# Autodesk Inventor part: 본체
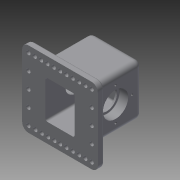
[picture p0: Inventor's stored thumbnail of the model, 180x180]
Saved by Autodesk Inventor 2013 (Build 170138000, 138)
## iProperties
Created: 2018-11
Part Number: 본체
Material: 일반
Document SubType Name: Modeling
Designer: Administrator
Density: 1 g/cm^3
Author: Administrator
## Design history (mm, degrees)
sketch "스케치1"
  geometry: L1 (60, -60)-(-60, -60); L2 (-60, -60)-(-60, 60); L3 (-60, 60)-(60, 60); L4 (60, 60)-(60, -60); 2 further points
  constraints: 8 end point, 2 parallel, 1 coincident, 1 horizontal, 1 perpendicular
  dimensions: "d0" = 120 distance of L3.end L1.start; "d2" = 120 distance between parallel lines of L2 L4; "d3" = 60 distance from line of point (0, 0) L4; "d4" = 60 distance from line of point (0, 0) L1
extrude "돌출1" new body sketch "스케치1" distance "d5" = 10; taper "d6" = 0 deg
sketch "스케치2"
  geometry: L1 (60, 60)-(-60, 60) reference; L2 (60, -60)-(60, 60) reference; L3 (-40, 40)-(40, 40); L4 (40, 40)-(40, -40); L5 (40, -40)-(-40, -40); L6 (-40, -40)-(-40, 40); 2 further points
  constraints: 8 end point, 2 parallel, 1 coincident, 1 horizontal, 1 perpendicular
  dimensions: "d7" = 80 distance between parallel lines of L4 L6; "d9" = 80 distance between parallel lines of L5 L3; "d10" = 20 distance between parallel lines of L1 L3; "d11" = 20 distance between parallel lines of L2 L4
extrude "돌출2" join sketch "스케치2" distance "d12" = 80; taper "d13" = 0 deg
sketch "스케치3"
  geometry: L1 (60, -60)-(60, 60) reference; L2 (60, 60)-(-60, 60) reference; L3 (-23, 30)-(23, 30); L4 (23, 30)-(23, -30); L5 (23, -30)-(-23, -30); L6 (-23, -30)-(-23, 30); 2 further points
  constraints: 8 end point, 2 parallel, 1 coincident, 1 horizontal, 1 perpendicular
  dimensions: "d14" = 46 distance between parallel lines of L4 L6; "d16" = 60 distance between parallel lines of L5 L3; "d17" = 30 distance between parallel lines of L2 L3; "d18" = 37 distance between parallel lines of L1 L4
extrude "돌출3" cut sketch "스케치3" distance "d19" = 80; taper "d20" = 0 deg
sketch "스케치4"
  geometry: C1 r 7.5 at (0, 0); 1 further point
  constraints: 1 centre point, 1 coincident
  dimensions: "d21" = 15 diameter of C1
extrude "돌출4" join sketch "스케치4" distance "d22" = 5; taper "d23" = 0 deg
sketch "스케치5"
  geometry: C1 r 7.5 at (0, 0) reference; C2 r 3 at (0, 0)
  constraints: 1 centre point, 1 coincident
  dimensions: "d24" = 6 diameter of C2
extrude "돌출5" cut sketch "스케치5" distance "d25" = 50; taper "d26" = 0 deg
sketch "스케치6"
  geometry: L1 (80, 0)-(0, 0) reference; L2 (80, 0)-(80, 80) reference; L3 (0, 80)-(80, 80) reference; L4 (0, 0)-(0, 80) reference; L5 (40, -10)-(40, 38); C1 r 20 at (40, 38)
  constraints: 2 end point, 1 centre point, 1 coincident, 1 parallel
  dimensions: "d27" = 48 distance of L5.start L5.end; "d28" = 40 diameter of C1
extrude "돌출6" cut sketch "스케치6" distance "d29" = 14; taper "d30" = 0 deg
sketch "스케치7"
  geometry: C1 r 20 at (0, 0) reference; C2 r 16.5 at (0, 0); 1 further point
  constraints: 1 centre point, 1 coincident
  dimensions: "d31" = 33 diameter of C2
extrude "돌출7" cut sketch "스케치7" distance "d32" = 3; taper "d33" = 0 deg
sketch "스케치9"
  geometry: L1 (40, 64)-(40, 12); C1 r 20 at (40, 38) reference; A1 r 26 centre (40, 38) between (40, 64) and (40, 12); 2 further points
  constraints: 2 coincident, 2 end point, 2 point on circle, 1 centre point
  dimensions: "d34" = 52 diameter of A1
hole "구멍1" sketch "스케치9" at (40, 64) diameter "d35" = 3.242; stored, may be unused: countersink angle "d39" = 82 deg, drill point angle "d41" = 118 deg; dims "d36" = 8, "d37" = 3.023, "d38" = 2, "d40" = 10
feature "스레드1" dims "d45" = 10, "d46" = 0
sketch "스케치10"
  geometry: L1 (-40, -40)-(-40, 40) reference; L2 (60, 60)-(-60, 60) reference; L3 (-60, 60)-(-60, -60) reference; L4 (60, -60)-(60, 60) reference; L5 (-60, 25)-(-40, 25); C1 r 3.3 at (-50, 50); C2 r 3.3 at (-39.046, 50); C3 r 3.3 at (-29.046, 50); C4 r 3.3 at (-19.046, 50); C5 r 3.3 at (-9.046, 50); C6 r 3.3 at (0, 50); C7 r 3.3 at (-50, 25); C8 r 3.3 at (-50, 0); C9 r 3.3 at (-50, -50); C10 r 3.3 at (-40, -50); C11 r 3.3 at (-30, -50); C12 r 3.3 at (-20, -50); C13 r 3.3 at (-10, -50); C14 r 3.3 at (0, -50); C15 r 3.3 at (-50, -25); C16 r 3.3 at (50, 50); C17 r 3.3 at (40, 50); C18 r 3.3 at (30, 50); C19 r 3.3 at (20, 50); C20 r 3.3 at (10, 50); C21 r 3.3 at (10, -50); C22 r 3.3 at (20, -50); C23 r 3.3 at (30, -50); C24 r 3.3 at (40, -50); C25 r 3.3 at (50, -50); C26 r 3.3 at (50, -25); C27 r 3.3 at (50, 25); C28 r 3.3 at (50, 0); 1 further point
  constraints: 28 centre point, 20 equal radius, 2 end point, 2 point on line, 1 midpoint, 1 perpendicular
  dimensions: "d54" = 6.6 diameter of C1; "d56" = 6.6 diameter of C3; "d57" = 6.6 diameter of C4; "d58" = 6.6 diameter of C5; "d59" = 6.6 diameter of C6; "d60" = 6.6 diameter of C7; "d61" = 6.6 diameter of C8; "d64" = 6.6 diameter of C15; "d67" = 35 distance between parallel lines of L2 L5; "d68" = 10 distance from line of C16.centre L2; "d69" = 10 distance from line of C16.centre L4; "d70" = 35 distance from line of C27.centre L2; "d71" = 10 distance from line of C27.centre L4; "d72" = 60 distance from line of C28.centre L2; "d73" = 10 distance from line of C28.centre L4; "d74" = 85 distance from line of C26.centre L2; "d75" = 10 distance from line of C26.centre L4; "d76" = 110 distance from line of C25.centre L2; "d77" = 10 distance from line of C25.centre L4; "d78" = 10 distance from line of C17.centre L2; "d79" = 20 distance from line of C17.centre L4; "d80" = 110 distance from line of C24.centre L2; "d81" = 20 distance from line of C24.centre L4; "d82" = 10 distance from line of C18.centre L2; "d83" = 30 distance from line of C18.centre L4; "d84" = 110 distance from line of C23.centre L2; "d85" = 30 distance from line of C23.centre L4; "d86" = 10 distance from line of C19.centre L2; "d87" = 40 distance from line of C19.centre L4; "d88" = 110 distance from line of C22.centre L2; "d89" = 40 distance from line of C22.centre L4; "d90" = 10 distance from line of C20.centre L2; "d91" = 50 distance from line of C20.centre L4; "d92" = 110 distance from line of C21.centre L2; "d93" = 50 distance from line of C21.centre L4; "d94" = 10 distance from line of C6.centre L2; "d95" = 60 distance from line of C6.centre L4; "d96" = 110 distance from line of C14.centre L2; "d97" = 60 distance from line of C14.centre L4; "d98" = 10 distance from line of C5.centre L2; "d99" = 69.04638 distance from line of C5.centre L4; "d100" = 110 distance from line of C13.centre L2; "d101" = 70 distance from line of C13.centre L4; "d102" = 10 distance from line of C4.centre L2; "d103" = 79.04638 distance from line of C4.centre L4; "d104" = 110 distance from line of C12.centre L2; "d105" = 80 distance from line of C12.centre L4; "d106" = 10 distance from line of C3.centre L2; "d107" = 89.04638 distance from line of C3.centre L4; "d108" = 110 distance from line of C11.centre L2; "d109" = 90 distance from line of C11.centre L4; "d110" = 10 distance from line of C2.centre L2; "d111" = 99.04638 distance from line of C2.centre L4; "d112" = 110 distance from line of C10.centre L2; "d113" = 100 distance from line of C10.centre L4; "d114" = 10 distance from line of C1.centre L2; "d115" = 110 distance from line of C1.centre L4; "d116" = 60 distance from line of C8.centre L2; "d117" = 110 distance from line of C8.centre L4; "d118" = 85 distance from line of C15.centre L2; "d119" = 110 distance from line of C15.centre L4; "d120" = 110 distance from line of C9.centre L2; "d121" = 110 distance from line of C9.centre L4
extrude "돌출8" cut sketch "스케치10" distance "d122" = 10; taper "d123" = 0 deg
fillet "모깎기1" dims "d124" = 3, "d125" = 8, "d126" = 10, "d127" = 0.6
fillet "모깎기2" dims "d128" = 3, "d129" = 8
sketch "스케치11"
  geometry: L1 (82, -82)-(-18, -82) reference; 2 further points
  constraints: 1 other
  dimensions: "d130" = 48 distance from line of L1 point (32, -34)
feature "엠보싱1" sketch "스케치11" dims "d2" = 120, "d131" = 0.5, "d132" = 0
node "솔리드1"
pattern_circular "원형 패턴1" dims angle "d43" = 360 deg
mirror "대칭1"
node "투영된 루프1"
